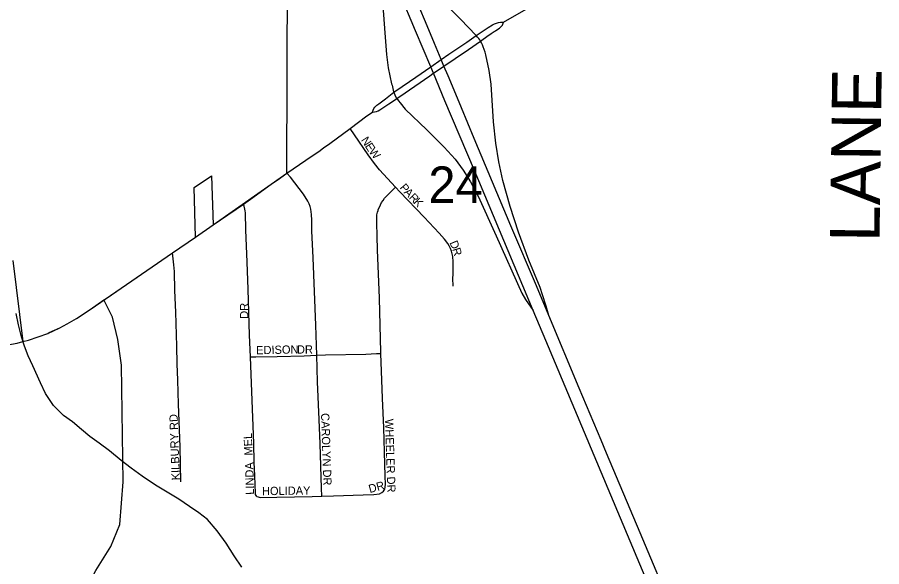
# Model space of a CAD drawing. Extents: x -97 to 34, y -21 to 22.
# Drawn here: x 7.621 to 8.613, y 19.498 to 20.128 of the extents above; entities that cross this region are included whole.
import ezdxf

# ---------------------------------------------------------------- set-up
doc = ezdxf.new("R2010")
doc.units = 0
for name, color, linetype in [('GM_X_Corporation', 7, 'Continuous'), ('GM_X_County_Road', 7, 'Continuous'), ('GM_X_County_Road_Text', 7, 'Continuous'), ('GM_X_Interchange_Ramps', 7, 'Continuous'), ('GM_X_Minor_River', 7, 'Continuous'), ('GM_X_Section_Text', 7, 'Continuous'), ('GM_X_State_Route', 7, 'Continuous'), ('GM_X_Township_Subdivision', 7, 'Continuous'), ('GM_X_Township_Subdivision_Text', 7, 'Continuous'), ('GM_X_US_Route', 7, 'Continuous')]:
    doc.layers.add(name, color=color, linetype=linetype)

msp = doc.modelspace()

# ---------------------------------------------------------------- linework, layer by layer
at = {"layer": 'GM_X_Corporation'}
msp.add_lwpolyline([(7.61568, 19.84901), (7.62745, 19.75611), (7.63379, 19.75789), (7.64484, 19.76174), (7.65589, 19.7656), (7.65763, 19.7664), (7.66984, 19.77204), (7.67812, 19.77635), (7.68348, 19.77952), (7.68885, 19.78268), (7.70446, 19.79298), (7.79902, 19.85789), (7.82534, 19.87578), (7.82399, 19.93282), (7.84369, 19.94625), (7.84577, 19.88989), (7.93024, 19.94922), (7.93158, 20.4045)], dxfattribs=at)
at = {"layer": 'GM_X_County_Road'}
msp.add_lwpolyline([(7.63138, 19.22008), (7.63831, 19.23373), (7.65137, 19.25264), (7.66742, 19.27182), (7.67877, 19.29113), (7.68573, 19.30703), (7.69047, 19.32503), (7.69262, 19.34363), (7.69318, 19.36493), (7.6935, 19.38342), (7.69258, 19.4218), (7.69435, 19.4483), (7.69987, 19.47278), (7.71092, 19.49368), (7.72821, 19.52127), (7.7387, 19.54621), (7.74234, 19.59536), (7.74061, 19.72923), (7.73628, 19.7586), (7.73012, 19.78408), (7.7203, 19.80385)], dxfattribs=at)
at = {"layer": 'GM_X_Interchange_Ramps'}
for points in [[(7.9811, 20.34308), (7.98592, 20.3266), (7.98991, 20.31464), (8.00985, 20.26477), (8.01807, 20.24129), (8.02603, 20.21446), (8.03267, 20.18727), (8.03741, 20.16285), (8.04033, 20.14128), (8.04259, 20.11027), (8.04443, 20.08546), (8.04657, 20.07007), (8.0505, 20.05183), (8.0509, 20.05024), (8.05224, 20.04434), (8.05307, 20.04214), (8.05457, 20.03817)], [(8.15041, 20.10364), (8.14898, 20.10531), (8.14739, 20.10707), (8.12968, 20.12612), (8.09906, 20.15663), (8.08669, 20.17041), (8.0772, 20.18257), (8.06878, 20.1955), (8.06017, 20.21187), (8.03713, 20.26271), (8.03063, 20.27566), (8.02073, 20.29522), (8.00654, 20.31919)], [(8.23083, 19.7862), (8.22796, 19.79691), (8.22372, 19.80979), (8.22091, 19.81807), (8.20777, 19.84969), (8.1959, 19.88164), (8.18644, 19.91116), (8.17819, 19.94103), (8.17351, 19.96221), (8.17001, 19.98361), (8.16728, 20.00826), (8.1646, 20.05155), (8.16251, 20.06689), (8.15853, 20.08506), (8.15766, 20.08813), (8.15675, 20.09116), (8.15565, 20.0943), (8.15471, 20.09661), (8.15378, 20.09883), (8.15241, 20.10085), (8.15156, 20.10211), (8.15041, 20.10364)], [(8.05457, 20.03817), (8.05603, 20.03547), (8.05636, 20.03497), (8.05823, 20.03224), (8.06009, 20.02992), (8.06619, 20.02284), (8.09092, 19.99901), (8.11082, 19.97918), (8.1233, 19.96521), (8.13269, 19.95276), (8.14098, 19.93955), (8.14964, 19.92295), (8.17035, 19.87749), (8.19975, 19.81164), (8.20399, 19.80447), (8.21297, 19.79176)]]:
    msp.add_lwpolyline(points, dxfattribs=at)
at = {"layer": 'GM_X_Minor_River'}
msp.add_lwpolyline([(7.87846, 19.49746), (7.86979, 19.51038), (7.86075, 19.52482), (7.85019, 19.53926), (7.83925, 19.55219), (7.82942, 19.55981), (7.81845, 19.56705), (7.80636, 19.57543), (7.79274, 19.58345), (7.7795, 19.59146), (7.76438, 19.60175), (7.75153, 19.61089), (7.74019, 19.61965), (7.72658, 19.6307), (7.71486, 19.63946), (7.70428, 19.64746), (7.69446, 19.65546), (7.68426, 19.66421), (7.67405, 19.67145), (7.66234, 19.68287), (7.6533, 19.69655), (7.64766, 19.7087), (7.63863, 19.72844), (7.63337, 19.73983), (7.62924, 19.75084), (7.62587, 19.76146), (7.62251, 19.7755), (7.61953, 19.7884)], dxfattribs=at)
at = {"layer": 'GM_X_State_Route'}
for points in [[(8.16953, 20.11273), (8.17101, 20.11365), (8.17406, 20.11552), (8.17615, 20.11746), (8.17756, 20.11903), (8.17865, 20.12247), (8.20481, 20.13736), (8.24034, 20.1622), (8.25199, 20.17053)], [(8.02866, 20.01945), (8.02926, 20.02146), (8.03008, 20.02332), (8.03127, 20.02503), (8.03231, 20.02614), (8.03365, 20.02734), (8.03566, 20.02877), (8.03888, 20.03124), (8.04335, 20.03466), (8.04729, 20.03768), (8.05307, 20.04214), (8.05524, 20.04377), (8.07828, 20.05931), (8.09535, 20.07119), (8.10737, 20.07956), (8.11627, 20.08576), (8.13666, 20.09966), (8.14739, 20.10707), (8.15192, 20.11018), (8.15446, 20.11189), (8.1577, 20.11402), (8.16131, 20.11631), (8.16625, 20.11935), (8.16848, 20.12064), (8.17067, 20.12152), (8.17302, 20.12228), (8.17552, 20.12262), (8.17865, 20.12247)], [(8.09444, 20.0611), (8.09793, 20.06351), (8.09844, 20.06386), (8.11053, 20.07202), (8.12349, 20.08076), (8.13879, 20.0912), (8.15241, 20.10085), (8.15394, 20.10189), (8.15983, 20.10605), (8.16486, 20.10959), (8.16827, 20.11194), (8.16953, 20.11273)], [(8.05636, 20.03497), (8.0567, 20.03517), (8.05986, 20.03718), (8.09444, 20.0611)], [(8.0414, 20.02483), (8.04259, 20.02563), (8.04717, 20.0287), (8.05257, 20.03231), (8.05636, 20.03497)], [(7.93024, 19.94922), (7.95935, 19.96935), (7.96676, 19.97433), (7.97244, 19.9783), (7.97951, 19.98338), (8.00289, 20.00067), (8.02215, 20.01491), (8.02866, 20.01945), (8.03074, 20.01974), (8.03312, 20.02012), (8.03484, 20.02079), (8.03692, 20.02198), (8.03921, 20.02337), (8.0414, 20.02483)], [(7.84577, 19.88988), (7.88061, 19.91391), (7.89139, 19.92134), (7.91224, 19.93653), (7.92195, 19.94332), (7.93024, 19.94922)], [(7.82534, 19.87578), (7.84577, 19.88988)], [(7.62744, 19.75611), (7.63379, 19.75789), (7.65588, 19.7656), (7.66984, 19.77204), (7.67812, 19.77635), (7.68885, 19.78268), (7.70446, 19.79298), (7.7203, 19.80385), (7.72291, 19.80565), (7.79902, 19.85789), (7.80727, 19.86355), (7.82534, 19.87578)], [(7.49, 19.74567), (7.52407, 19.74682), (7.54423, 19.74765), (7.54885, 19.74785), (7.58909, 19.74947), (7.59338, 19.74978), (7.5966, 19.75005), (7.59805, 19.75024), (7.60271, 19.75087), (7.60744, 19.75164), (7.61412, 19.75303), (7.62074, 19.75449), (7.62744, 19.75611)]]:
    msp.add_lwpolyline(points, dxfattribs=at)
at = {"layer": 'GM_X_Township_Subdivision'}
for points in [[(8.05506, 19.93324), (8.03668, 19.95316), (8.03079, 19.96032), (8.02343, 19.97028), (8.00777, 19.99345), (8.00289, 20.00067)], [(7.96469, 19.74046), (7.96331, 19.77514), (7.96044, 19.85236), (7.95901, 19.88315), (7.95895, 19.89559), (7.9586, 19.90188), (7.95775, 19.90815), (7.95693, 19.91126), (7.95574, 19.91425), (7.9543, 19.91709), (7.94932, 19.92509), (7.93438, 19.94465), (7.93024, 19.94922)], [(8.03488, 19.90641), (8.03516, 19.90734), (8.03754, 19.91292), (8.039, 19.91557), (8.04065, 19.91811), (8.04247, 19.92052), (8.04447, 19.92279), (8.05105, 19.92927), (8.05506, 19.93324)], [(8.12092, 19.83305), (8.12106, 19.84748), (8.12063, 19.8538), (8.12008, 19.85694), (8.11922, 19.86002), (8.11805, 19.863), (8.11659, 19.86583), (8.11492, 19.86853), (8.11112, 19.87358), (8.10487, 19.88058), (8.08788, 19.89877), (8.06004, 19.92806), (8.05506, 19.93324)], [(7.88852, 19.73847), (7.88749, 19.76352), (7.88578, 19.81623), (7.88478, 19.84723), (7.88326, 19.88442), (7.88268, 19.90381), (7.88247, 19.90612), (7.88215, 19.90815), (7.88129, 19.91137), (7.88061, 19.91391)], [(8.03818, 19.74259), (8.03812, 19.74398), (8.0375, 19.77491), (8.03643, 19.80585), (8.03413, 19.86149), (8.03399, 19.87695), (8.03335, 19.89244), (8.03337, 19.89853), (8.03367, 19.90152), (8.03429, 19.90446), (8.03488, 19.90641)], [(7.80854, 19.59522), (7.80779, 19.63545), (7.80592, 19.68445), (7.80498, 19.71201), (7.80453, 19.73051), (7.80393, 19.75091), (7.80268, 19.78989), (7.80168, 19.81477), (7.80119, 19.83643), (7.80069, 19.84423), (7.79987, 19.85097), (7.79902, 19.85789)], [(8.12118, 19.81956), (8.12087, 19.82882), (8.12092, 19.83305)], [(7.88852, 19.73847), (7.89455, 19.73856), (7.91921, 19.73892), (7.95003, 19.73975), (7.96469, 19.74046)], [(7.96469, 19.74046), (7.97467, 19.74094), (8.02091, 19.74181), (8.03324, 19.74237), (8.03818, 19.74259)], [(7.97048, 19.57892), (7.97015, 19.58802), (7.96833, 19.63901), (7.96741, 19.66697), (7.96555, 19.71017), (7.96469, 19.74046)], [(8.04125, 19.58446), (8.04261, 19.58669), (8.04305, 19.58915), (8.04335, 19.59244), (8.04317, 19.60172), (8.0422, 19.62957), (8.04135, 19.65741), (8.04008, 19.69143), (8.03895, 19.72236), (8.03818, 19.74259)], [(7.89593, 19.57858), (7.89489, 19.57954), (7.89438, 19.58089), (7.89415, 19.58211), (7.89339, 19.60236), (7.89278, 19.61787), (7.89236, 19.63956), (7.8902, 19.69843), (7.88852, 19.73847)], [(7.97048, 19.57892), (7.98381, 19.57929), (8.01783, 19.58023), (8.03023, 19.5809), (8.03647, 19.58171), (8.03926, 19.58298), (8.04125, 19.58446)], [(7.89593, 19.57858), (7.89715, 19.578), (7.89857, 19.57755), (7.90016, 19.57737), (7.91885, 19.57788), (7.9591, 19.5786), (7.97048, 19.57892)]]:
    msp.add_lwpolyline(points, dxfattribs=at)
at = {"layer": 'GM_X_US_Route'}
for points in [[(8.08922, 20.12279), (8.08278, 20.13813), (8.04175, 20.23548), (8.01766, 20.29276), (8.00654, 20.31919), (7.96775, 20.41139)], [(8.3575, 19.44807), (8.22737, 19.75743), (8.21297, 19.79176), (8.1793, 19.87205), (8.14554, 19.95224), (8.11167, 20.03238), (8.09844, 20.06386), (8.09535, 20.07119), (8.07794, 20.11258), (8.04193, 20.19856)], [(8.09968, 20.09788), (8.08922, 20.12279)], [(8.11633, 20.05822), (8.11525, 20.06079), (8.11053, 20.07202), (8.10737, 20.07956), (8.09968, 20.09788)], [(8.13067, 20.02409), (8.11633, 20.05822)], [(8.29083, 19.6432), (8.26569, 19.70273), (8.23083, 19.7862), (8.2166, 19.82027), (8.18735, 19.88888), (8.14534, 19.98917), (8.13067, 20.02409)], [(8.50657, 19.1296), (8.50093, 19.14326), (8.49709, 19.15257), (8.46779, 19.22182), (8.4611, 19.23778), (8.43526, 19.30001), (8.40247, 19.37747), (8.37419, 19.44488), (8.33569, 19.53666), (8.29713, 19.6283), (8.29083, 19.6432)]]:
    msp.add_lwpolyline(points, dxfattribs=at)

# ---------------------------------------------------------------- texts
at = {"layer": 'GM_X_County_Road_Text'}
msp.add_text('LANE', height=0.056818, rotation=89.25921, dxfattribs=at).set_placement((8.6103, 19.8701))
at = {"layer": 'GM_X_Section_Text'}
msp.add_text('24', height=0.041856, rotation=0.00001, dxfattribs=at).set_placement((8.09265, 19.91515))
at = {"layer": 'GM_X_Township_Subdivision_Text'}
for s, rotation, p in [('N', 302.41085, (8.01499, 19.98739)), ('E', 302.37899, (8.01946, 19.98035)), ('W', 308.69477, (8.02368, 19.97381)), ('P', 310.39681, (8.05918, 19.93239)), ('A', 313.75703, (8.0639, 19.92687)), ('R', 314.06444, (8.0697, 19.9208)), ('K', 314.05727, (8.07492, 19.91542)), ('D', 292.23156, (8.11677, 19.86968)), ('R', 286.9063, (8.11985, 19.86218)), ('DR', 90, (7.88591, 19.78228)), ('EDISON', 1.12271, (7.89512, 19.74156)), ('DR', 0.00001, (7.94182, 19.74239)), ('KILBURY RD', 92.04421, (7.80754, 19.59721)), ('CAROLYN DR', 271.91005, (7.96944, 19.67396)), ('WHEELER DR', 271.92963, (8.04277, 19.66729)), ('MEL', 91.97365, (7.89091, 19.62555)), ('LINDA', 91.30128, (7.89258, 19.58057)), ('HOLIDAY', 0.90888, (7.90179, 19.57989)), ('DR', 15.51472, (8.02551, 19.58233))]:
    msp.add_text(s, height=0.00947, rotation=rotation, dxfattribs=at).set_placement(p)

doc.saveas('drawing.dxf')
